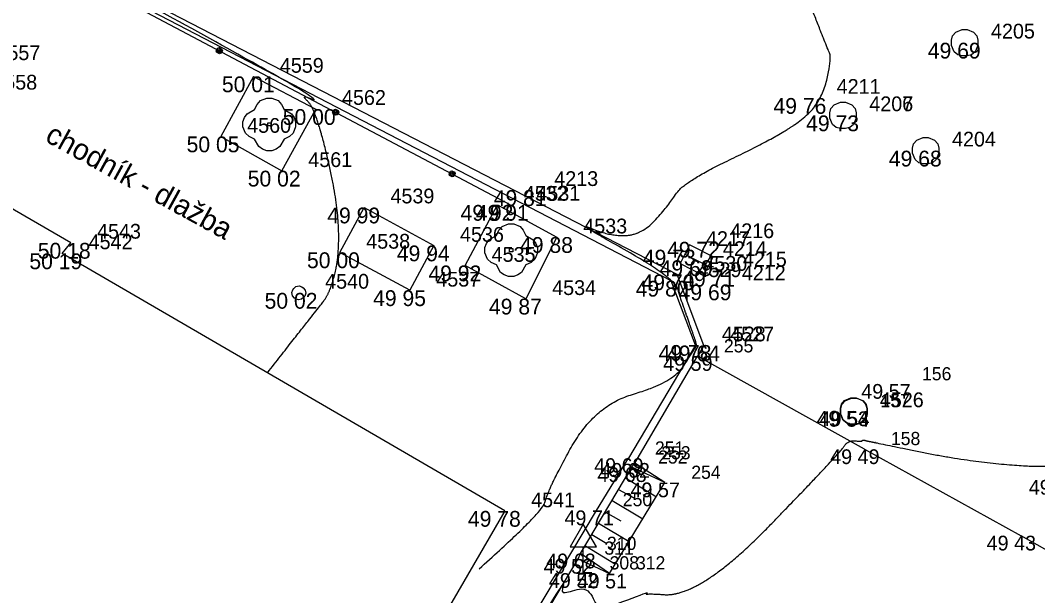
# Model space of a CAD drawing. Extents: x -704017 to -701500, y -1008977 to -1008450.
# Drawn here: x -701778.61 to -701759.29, y -1008950.57 to -1008939.65 of the extents above; entities that cross this region are included whole.
import ezdxf

# ---------------------------------------------------------------- set-up
doc = ezdxf.new("R2010")
doc.units = 0
for name, color, linetype in [('Z_body', 7, 'Continuous'), ('Z_body_cisla', 7, 'Continuous'), ('Z_body_vysky', 7, 'Continuous'), ('Z_budovy', 7, 'Continuous'), ('Z_dopravni_znaceni', 7, 'Continuous'), ('Z_komunikace', 7, 'Continuous'), ('Z_obruby', 7, 'Continuous'), ('Z_popis', 7, 'Continuous'), ('Z_rozhrani_ploch', 7, 'Continuous'), ('Z_site_znaky_kanalizace', 7, 'Continuous'), ('Z_site_znaky_vodovod', 7, 'Continuous'), ('Z_teren_hrany_paty', 7, 'Continuous'), ('Z_vrstevnice_hlavni', 7, 'Continuous'), ('Z_vrstevnice_vedlejsi', 7, 'Continuous'), ('Z_zabradli', 7, 'Continuous'), ('Z_zelen_jednotliva', 7, 'Continuous')]:
    doc.layers.add(name, color=color, linetype=linetype)

# ---------------------------------------------------------------- blocks, each defined once
blk = doc.blocks.new('POINT_DISPLAY')
blk.add_line((0, 0), (0, 0))
blk = doc.blocks.new('Z530')
for p, q in [((-0.05, 0.03), (-0.03, 0.05)), ((-0.05, -0.03), (-0.05, 0.03)), ((-0.03, 0.05), (0.03, 0.05)), ((-0.03, -0.03), (-0.03, 0.03)), ((-0.03, 0.03), (0.03, 0.03)), ((-0.03, -0.03), (0.03, 0.03)), ((0.03, 0.05), (0.05, 0.03)), ((0.03, 0.03), (0.03, -0.03)), ((0.05, 0.03), (0.05, -0.03)), ((-0.03, -0.05), (-0.05, -0.03)), ((0.03, -0.03), (-0.03, -0.03)), ((0.03, -0.05), (-0.03, -0.05)), ((0.05, -0.03), (0.03, -0.05))]:
    blk.add_line(p, q)
blk = doc.blocks.new('Z527')
for p, q in [((0, 0.93), (-0.25, 0.5)), ((0.25, 0.5), (0, 0.93)), ((-0.25, 0.5), (0.25, 0.5)), ((0, 0), (0, 0.5)), ((-0.13, 0), (0.13, 0))]:
    blk.add_line(p, q)
blk = doc.blocks.new('Z620')
for p, q in [((-0.23, 0.13), (-0.17, 0.2)), ((-0.17, 0.2), (-0.05, 0.25)), ((-0.05, 0.25), (0.05, 0.25)), ((0.05, 0.25), (0.17, 0.2)), ((0.17, 0.2), (0.23, 0.13)), ((-0.25, 0.05), (-0.23, 0.13)), ((-0.25, -0.05), (-0.25, 0.05)), ((0.23, 0.13), (0.25, 0.05)), ((0.25, 0.05), (0.25, -0.05)), ((-0.2, -0.17), (-0.25, -0.05)), ((-0.13, -0.23), (-0.2, -0.17)), ((0.2, -0.17), (0.13, -0.23)), ((0.25, -0.05), (0.2, -0.17)), ((-0.05, -0.25), (-0.13, -0.23)), ((0.05, -0.25), (-0.05, -0.25)), ((0.13, -0.23), (0.05, -0.25))]:
    blk.add_line(p, q)
blk = doc.blocks.new('Z38')
for p, q in [((0.25, 0.2), (-0.25, 0.2)), ((-0.25, 0.2), (-0.25, -0.2)), ((0.25, -0.2), (0.25, 0.2)), ((-0.25, 0), (0.25, 0)), ((-0.25, -0.2), (0.25, -0.2))]:
    blk.add_line(p, q)
blk = doc.blocks.new('Z614')
for p, q in [((-0.13, 0.03), (-0.1, 0.08)), ((-0.13, -0.03), (-0.13, 0.03)), ((-0.1, 0.08), (-0.08, 0.1)), ((-0.08, 0.1), (-0.03, 0.13)), ((-0.03, 0.13), (0.03, 0.13)), ((0.03, 0.13), (0.08, 0.1)), ((0.08, 0.1), (0.1, 0.08)), ((0.1, 0.08), (0.13, 0.03)), ((0.13, 0.03), (0.13, -0.03)), ((-0.1, -0.08), (-0.13, -0.03)), ((-0.08, -0.1), (-0.1, -0.08)), ((-0.03, -0.13), (-0.08, -0.1)), ((0.03, -0.13), (-0.03, -0.13)), ((0.08, -0.1), (0.03, -0.13)), ((0.1, -0.08), (0.08, -0.1)), ((0.13, -0.03), (0.1, -0.08))]:
    blk.add_line(p, q)
blk = doc.blocks.new('Z24')
for p, q in [((-0.23, 0.38), (-0.17, 0.45)), ((-0.17, 0.45), (-0.05, 0.5)), ((-0.05, 0.5), (0.05, 0.5)), ((0.05, 0.5), (0.17, 0.45)), ((0.17, 0.45), (0.23, 0.38)), ((-0.47, 0.13), (-0.42, 0.2)), ((-0.42, 0.2), (-0.28, 0.28)), ((-0.28, 0.28), (-0.23, 0.38)), ((0.23, 0.38), (0.28, 0.28)), ((0.28, 0.28), (0.42, 0.2)), ((0.42, 0.2), (0.47, 0.13)), ((-0.5, 0.05), (-0.47, 0.13)), ((-0.5, -0.05), (-0.5, 0.05)), ((-0.03, -0.03), (-0.03, 0.03)), ((-0.03, 0.03), (0.03, 0.03)), ((0.03, 0.03), (0.03, -0.03)), ((0.47, 0.13), (0.5, 0.05)), ((0.5, 0.05), (0.5, -0.05)), ((-0.45, -0.17), (-0.5, -0.05)), ((-0.38, -0.23), (-0.45, -0.17)), ((0.03, -0.03), (-0.03, -0.03)), ((0.45, -0.17), (0.38, -0.23)), ((0.5, -0.05), (0.45, -0.17)), ((-0.28, -0.28), (-0.38, -0.23)), ((-0.2, -0.42), (-0.28, -0.28)), ((0.28, -0.28), (0.2, -0.42)), ((0.38, -0.23), (0.28, -0.28)), ((-0.13, -0.47), (-0.2, -0.42)), ((-0.05, -0.5), (-0.13, -0.47)), ((0.05, -0.5), (-0.05, -0.5)), ((0.13, -0.47), (0.05, -0.5)), ((0.2, -0.42), (0.13, -0.47))]:
    blk.add_line(p, q)

msp = doc.modelspace()

# ---------------------------------------------------------------- linework, layer by layer
at = {"layer": 'Z_budovy'}
for p, q in [((-701777.65, -1008943.87), (-701780.37, -1008942.3)), ((-701777.81, -1008944.07), (-701777.65, -1008943.87)), ((-701769.41, -1008948.96), (-701777.81, -1008944.07)), ((-701769.41, -1008948.96), (-701770.98, -1008951.66))]:
    msp.add_line(p, q, dxfattribs=at)
at = {"layer": 'Z_komunikace'}
for p, q in [((-701766.14, -1008944.47), (-701777.69, -1008938.5)), ((-701765.63, -1008945.82), (-701766.14, -1008944.47)), ((-701765.63, -1008945.82), (-701765.75, -1008946.02)), ((-701766.94, -1008948.05), (-701765.75, -1008946.02)), ((-701767.97, -1008949.77), (-701767, -1008948.13)), ((-701767, -1008948.13), (-701766.94, -1008948.05)), ((-701768.77, -1008951.13), (-701768.02, -1008949.87)), ((-701768.02, -1008949.87), (-701767.97, -1008949.77))]:
    msp.add_line(p, q, dxfattribs=at)
at = {"layer": 'Z_obruby'}
for p, q in [((-701766.25, -1008944.59), (-701777.73, -1008938.63)), ((-701765.79, -1008945.81), (-701766.25, -1008944.59)), ((-701765.79, -1008945.81), (-701767.06, -1008947.96)), ((-701767.67, -1008948.95), (-701767.06, -1008947.96)), ((-701774.46, -1008960.32), (-701767.67, -1008948.95))]:
    msp.add_line(p, q, dxfattribs=at)
at = {"layer": 'Z_rozhrani_ploch'}
for p, q in [((-701774.18, -1008940.71), (-701774.8, -1008941.85)), ((-701774.18, -1008940.71), (-701773, -1008941.33)), ((-701773.64, -1008942.5), (-701773, -1008941.33)), ((-701774.8, -1008941.85), (-701773.64, -1008942.5)), ((-701772.54, -1008944.05), (-701772.08, -1008943.2)), ((-701772.08, -1008943.2), (-701770.76, -1008943.92)), ((-701770.16, -1008944.3), (-701769.55, -1008943.15)), ((-701769.55, -1008943.15), (-701768.42, -1008943.76)), ((-701768.42, -1008943.76), (-701769.01, -1008944.93)), ((-701770.76, -1008943.92), (-701771.21, -1008944.77)), ((-701771.21, -1008944.77), (-701772.54, -1008944.05)), ((-701769.01, -1008944.93), (-701770.16, -1008944.3)), ((-701762.58, -1008947.79), (-701765.75, -1008946.02)), ((-701762.58, -1008947.79), (-701759.61, -1008949.43)), ((-701750.9, -1008954.36), (-701759.61, -1008949.43))]:
    msp.add_line(p, q, dxfattribs=at)
at = {"layer": 'Z_teren_hrany_paty'}
for p, q in [((-701766.37, -1008948.42), (-701767, -1008948.13)), ((-701766.37, -1008948.42), (-701766.94, -1008948.05)), ((-701767.12, -1008948.33), (-701766.53, -1008948.69)), ((-701767.42, -1008950.15), (-701766.37, -1008948.42)), ((-701767.25, -1008948.55), (-701766.95, -1008948.72)), ((-701767.37, -1008948.76), (-701766.79, -1008949.11)), ((-701767.5, -1008948.98), (-701767.21, -1008949.15)), ((-701767.63, -1008949.19), (-701767.05, -1008949.54)), ((-701767.76, -1008949.41), (-701767.47, -1008949.58)), ((-701767.88, -1008949.62), (-701767.31, -1008949.97)), ((-701768.02, -1008949.87), (-701767.42, -1008950.15)), ((-701767.42, -1008950.15), (-701767.97, -1008949.77))]:
    msp.add_line(p, q, dxfattribs=at)
at = {"layer": 'Z_vrstevnice_hlavni'}
msp.add_open_spline([(-701773.917, -1008946.336), (-701772.994, -1008945.165), (-701772.717, -1008944.806), (-701772.54, -1008944.05), (-701772.6, -1008942.967), (-701773, -1008941.33), (-701773.298, -1008941.037), (-701772.919, -1008941.213), (-701773.425, -1008940.865), (-701777.693, -1008938.51), (-701778.097, -1008938.29), (-701778.007, -1008938.16), (-701776.67, -1008936.595), (-701775.26, -1008935.28), (-701775.197, -1008934.539), (-701775.26, -1008930.72), (-701775.36, -1008930.56), (-701771.04, -1008932.656), (-701770.3, -1008933.02), (-701769.763, -1008932.053), (-701769.344, -1008931.385), (-701769.32, -1008931.353), (-701769.078, -1008931.437), (-701768.6, -1008930.79), (-701767.948, -1008929.88), (-701767.142, -1008929.526), (-701766.83, -1008929.018)], degree=2, dxfattribs=at)
at = {"layer": 'Z_vrstevnice_vedlejsi'}
for points in [[(-701769.899, -1008950.059), (-701768.664, -1008948.956), (-701768.627, -1008948.627), (-701767.71, -1008946.95), (-701766.213, -1008946.527), (-701765.784, -1008945.843), (-701765.756, -1008945.812), (-701766.056, -1008944.974), (-701766.195, -1008944.53), (-701768.131, -1008943.441), (-701767.426, -1008943.743), (-701766.81, -1008943.718), (-701766.285, -1008943.142), (-701766.013, -1008942.708), (-701764.115, -1008941.802), (-701763.403, -1008941.23), (-701763.197, -1008940.343), (-701763.305, -1008940.153), (-701764.395, -1008937.27), (-701764.286, -1008936.614), (-701764.083, -1008936.371), (-701763.132, -1008936.744), (-701763.328, -1008936.613), (-701762.423, -1008936.934), (-701762.255, -1008936.983), (-701762.188, -1008936.853), (-701762.323, -1008937.228), (-701759.557, -1008938.62), (-701754.183, -1008941.372), (-701753.284, -1008941.824), (-701752.163, -1008942.388), (-701752.25, -1008942.19), (-701751.587, -1008942.205), (-701748.992, -1008941.797)], [(-701773.971, -1008959.221), (-701773.611, -1008958.899), (-701768.633, -1008950.858), (-701768.32, -1008950.374), (-701768.26, -1008950.536), (-701767.757, -1008950.395), (-701767.625, -1008950.96), (-701767.096, -1008950.484), (-701765.713, -1008950.612), (-701763.054, -1008947.869), (-701762.897, -1008947.613), (-701762.622, -1008947.644), (-701762.63, -1008947.61), (-701762.506, -1008947.635), (-701760.8, -1008947.99), (-701759.208, -1008948.143), (-701758.947, -1008948.041), (-701758.388, -1008948.143), (-701758.235, -1008948.241), (-701751.691, -1008949.254), (-701747.637, -1008948.233), (-701746.394, -1008948.75), (-701743.001, -1008950.306), (-701742.288, -1008950.624), (-701736.747, -1008953.52), (-701735.858, -1008954.034), (-701735.46, -1008954.08), (-701735.395, -1008953.825), (-701735.333, -1008953.766), (-701735.151, -1008953.611), (-701734.606, -1008953.07), (-701731.409, -1008949.369), (-701730.446, -1008948.79), (-701730.434, -1008950.022), (-701730.433, -1008950.432), (-701730.287, -1008951.52), (-701730.154, -1008952.408), (-701730.018, -1008952.903), (-701729.76, -1008953.885), (-701728.989, -1008953.081), (-701728.637, -1008952.767), (-701728.025, -1008951.97), (-701727.684, -1008951.31), (-701724.593, -1008947.235), (-701724.318, -1008946.646), (-701723.939, -1008946.078), (-701722.809, -1008944.781), (-701722.509, -1008944.53), (-701721.936, -1008943.957), (-701721.659, -1008943.897), (-701721.075, -1008943.473), (-701720.79, -1008943.82), (-701719.4, -1008944.98)]]:
    msp.add_open_spline(points, degree=2, dxfattribs=at)
at = {"layer": 'Z_zabradli'}
msp.add_line((-701769.31, -1008943.15), (-701777.73, -1008938.69), dxfattribs=at)

# ---------------------------------------------------------------- block references
at = {"layer": 'Z_body'}
for p in [(-701760.68, -1008940.07), (-701774.18, -1008940.71), (-701763.61, -1008941.12), (-701773, -1008941.33), (-701762.99, -1008941.45), (-701762.99, -1008941.45), (-701774.8, -1008941.85), (-701761.42, -1008942.12), (-701773.64, -1008942.5), (-701768.97, -1008942.87), (-701772.08, -1008943.2), (-701769.55, -1008943.15), (-701769.31, -1008943.15), (-701768.42, -1008943.76), (-701777.65, -1008943.87), (-701770.76, -1008943.92), (-701765.63, -1008943.85), (-701777.81, -1008944.07), (-701772.54, -1008944.05), (-701766.09, -1008944), (-701770.16, -1008944.3), (-701765.77, -1008944.2), (-701766.14, -1008944.47), (-701765.39, -1008944.4), (-701766.25, -1008944.59), (-701765.41, -1008944.66), (-701773.32, -1008944.82), (-701771.21, -1008944.77), (-701769.01, -1008944.93), (-701765.79, -1008945.81), (-701765.63, -1008945.82), (-701765.75, -1008946.02), (-701761.99, -1008946.55), (-701762.79, -1008947.06), (-701762.78, -1008947.07), (-701762.58, -1008947.79), (-701767.06, -1008947.96), (-701767, -1008948.13), (-701766.94, -1008948.05), (-701766.37, -1008948.42), (-701769.41, -1008948.96), (-701767.67, -1008948.95), (-701759.61, -1008949.43), (-701768.02, -1008949.87), (-701767.97, -1008949.77), (-701767.92, -1008950.14), (-701767.42, -1008950.15)]:
    msp.add_blockref('POINT_DISPLAY', p, dxfattribs=at)
at = {"layer": 'Z_dopravni_znaceni'}
msp.add_blockref('Z527', (-701767.92, -1008950.14), dxfattribs=at)
at = {"layer": 'Z_site_znaky_kanalizace'}
for p in [(-701760.68, -1008940.07), (-701762.99, -1008941.45), (-701761.42, -1008942.12), (-701762.79, -1008947.06), (-701762.78, -1008947.07)]:
    msp.add_blockref('Z620', p, dxfattribs=at)
at = {"layer": 'Z_site_znaky_kanalizace', "rotation": -27.000000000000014}
msp.add_blockref('Z38', (-701765.77, -1008944.2), dxfattribs=at)
at = {"layer": 'Z_site_znaky_vodovod', "rotation": 10.799999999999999}
msp.add_blockref('Z614', (-701773.32, -1008944.82), dxfattribs=at)
at = {"layer": 'Z_zabradli', "rotation": 152.1}
for p in [(-701774.83, -1008940.22), (-701772.62, -1008941.39), (-701770.41, -1008942.56)]:
    msp.add_blockref('Z530', p, dxfattribs=at)
at = {"layer": 'Z_zelen_jednotliva'}
for p in [(-701773.88, -1008941.62), (-701769.29, -1008944.01)]:
    msp.add_blockref('Z24', p, dxfattribs=at)

# ---------------------------------------------------------------- texts
at = {"layer": 'Z_body_cisla'}
for s, height, p in [('4205', 0.28, (-701760.18, -1008939.99)), ('4557', 0.28, (-701779.06, -1008940.4)), ('4559', 0.28, (-701773.68, -1008940.64)), ('4558', 0.28, (-701779.12, -1008940.96)), ('4211', 0.28, (-701763.11, -1008941.04)), ('4562', 0.28, (-701772.5, -1008941.25)), ('4206', 0.28, (-701762.49, -1008941.37)), ('4207', 0.28, (-701762.49, -1008941.37)), ('4560', 0.28, (-701774.3, -1008941.78)), ('4204', 0.28, (-701760.92, -1008942.04)), ('4561', 0.28, (-701773.14, -1008942.43)), ('4213', 0.28, (-701768.47, -1008942.79)), ('4532', 0.28, (-701769.05, -1008943.07)), ('4531', 0.28, (-701768.81, -1008943.07)), ('4539', 0.28, (-701771.58, -1008943.12)), ('4543', 0.28, (-701777.15, -1008943.79)), ('4536', 0.28, (-701770.26, -1008943.85)), ('4533', 0.28, (-701767.92, -1008943.69)), ('4216', 0.28, (-701765.13, -1008943.78)), ('4542', 0.28, (-701777.31, -1008943.99)), ('4538', 0.28, (-701772.04, -1008943.98)), ('4217', 0.28, (-701765.59, -1008943.93)), ('4535', 0.28, (-701769.66, -1008944.23)), ('4214', 0.28, (-701765.27, -1008944.12)), ('4530', 0.28, (-701765.64, -1008944.4)), ('4215', 0.28, (-701764.89, -1008944.32)), ('4529', 0.28, (-701765.75, -1008944.52)), ('4212', 0.28, (-701764.91, -1008944.58)), ('4540', 0.28, (-701772.82, -1008944.74)), ('4537', 0.28, (-701770.71, -1008944.7)), ('4534', 0.28, (-701768.51, -1008944.86)), ('4528', 0.28, (-701765.29, -1008945.74)), ('4527', 0.28, (-701765.13, -1008945.74)), ('255', 0.25, (-701765.25, -1008945.95)), ('156', 0.25, (-701761.49, -1008946.48)), ('4526', 0.28, (-701762.29, -1008946.99)), ('157', 0.25, (-701762.28, -1008946.99)), ('251', 0.25, (-701766.56, -1008947.89)), ('158', 0.25, (-701762.08, -1008947.71)), ('252', 0.25, (-701766.5, -1008948.06)), ('253', 0.25, (-701766.44, -1008947.98)), ('254', 0.25, (-701765.87, -1008948.35)), ('4541', 0.28, (-701768.91, -1008948.89)), ('250', 0.25, (-701767.17, -1008948.87)), ('311', 0.25, (-701767.52, -1008949.79)), ('310', 0.25, (-701767.47, -1008949.7)), ('308', 0.25, (-701767.42, -1008950.07)), ('312', 0.25, (-701766.92, -1008950.07))]:
    msp.add_text(s, height=height, dxfattribs=at).set_placement(p)
at = {"layer": 'Z_body_vysky'}
for s, height, p in [('49 69', 0.3, (-701761.38, -1008940.37)), ('50 01', 0.3, (-701774.78, -1008941.01)), ('49 76', 0.3, (-701764.31, -1008941.42)), ('50 00', 0.3, (-701773.625, -1008941.63)), ('49 73', 0.3, (-701763.69, -1008941.75)), ('49 73', 0.3, (-701763.69, -1008941.75)), ('50 05', 0.3, (-701775.45, -1008942.15)), ('49 68', 0.3, (-701762.12, -1008942.42)), ('50 02', 0.3, (-701774.29, -1008942.8)), ('49 81', 0.3, (-701769.62, -1008943.17)), ('49 99', 0.3, (-701772.78, -1008943.5)), ('49 92', 0.3, (-701770.25, -1008943.45)), ('49 91', 0.3, (-701769.96, -1008943.45)), ('49 88', 0.3, (-701769.12, -1008944.06)), ('50 18', 0.3, (-701778.275, -1008944.17)), ('49 94', 0.3, (-701771.46, -1008944.22)), ('49 72', 0.3, (-701766.33, -1008944.15)), ('50 19', 0.3, (-701778.435, -1008944.37)), ('50 00', 0.3, (-701773.165, -1008944.35)), ('49 73', 0.3, (-701766.79, -1008944.3)), ('49 92', 0.3, (-701770.86, -1008944.6)), ('49 69', 0.3, (-701766.47, -1008944.5)), ('49 70', 0.3, (-701766.815, -1008944.77)), ('49 71', 0.3, (-701766.04, -1008944.7)), ('49 80', 0.3, (-701766.925, -1008944.89)), ('49 69', 0.3, (-701766.11, -1008944.96)), ('50 02', 0.3, (-701773.97, -1008945.12)), ('49 95', 0.3, (-701771.91, -1008945.07)), ('49 87', 0.3, (-701769.71, -1008945.23)), ('49 78', 0.3, (-701766.49, -1008946.11)), ('49 64', 0.3, (-701766.33, -1008946.12)), ('49 59', 0.28, (-701766.403, -1008946.3)), ('49 57', 0.28, (-701762.643, -1008946.83)), ('49 54', 0.3, (-701763.49, -1008947.36)), ('49 53', 0.28, (-701763.433, -1008947.35)), ('49 49', 0.28, (-701763.233, -1008948.07)), ('49 69', 0.28, (-701767.713, -1008948.24)), ('49 68', 0.28, (-701767.653, -1008948.41)), ('49 62', 0.28, (-701767.593, -1008948.33)), ('49 49', 0.28, (-701759.463, -1008948.65)), ('49 57', 0.28, (-701767.023, -1008948.7)), ('49 78', 0.3, (-701770.11, -1008949.26)), ('49 71', 0.28, (-701768.277, -1008949.23)), ('49 43', 0.28, (-701760.263, -1008949.71)), ('49 68', 0.28, (-701768.623, -1008950.05)), ('49 52', 0.28, (-701768.673, -1008950.15)), ('49 52', 0.28, (-701768.573, -1008950.42)), ('49 51', 0.28, (-701768.027, -1008950.43))]:
    msp.add_text(s, height=height, dxfattribs=at).set_placement(p)
at = {"layer": 'Z_popis'}
msp.add_text('chodník - dlažba', height=0.4, rotation=331.2, dxfattribs=at).set_placement((-701778.16, -1008941.93))

doc.saveas('drawing.dxf')
